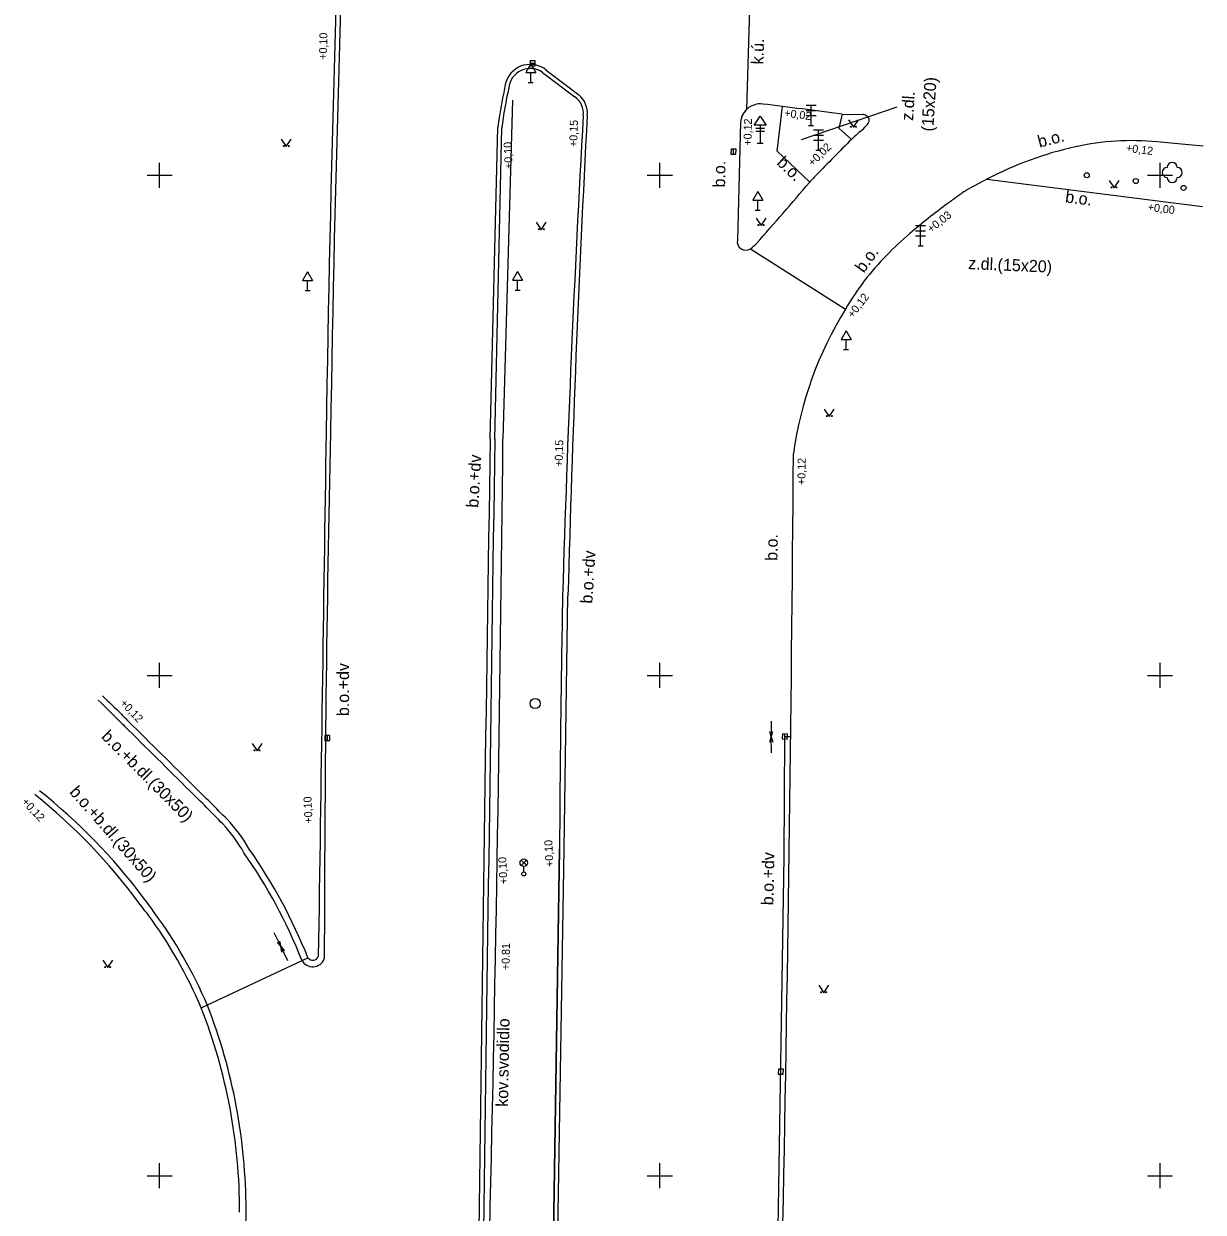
# Model space of a CAD drawing. Extents: x -599151 to -598424, y -1163476 to -1161924.
# Drawn here: x -598681.8 to -598622.8, y -1162451.8 to -1162392.4 of the extents above; entities that cross this region are included whole.
import ezdxf

# ---------------------------------------------------------------- set-up
doc = ezdxf.new("R2010")
doc.units = 0
for name, color, linetype in [('Vrstva 14', 7, 'Continuous'), ('Vrstva 15', 7, 'Continuous'), ('Vrstva 19', 7, 'Continuous'), ('Vrstva 21', 7, 'Continuous'), ('Vrstva 25', 7, 'Continuous'), ('Vrstva 29', 7, 'Continuous'), ('Vrstva 44', 7, 'Continuous'), ('Vrstva 49', 7, 'Continuous'), ('Vrstva 50', 7, 'Continuous'), ('Vrstva 62', 7, 'Continuous'), ('Vrstva 63', 7, 'Continuous'), ('Vrstva 7', 7, 'Continuous')]:
    doc.layers.add(name, color=color, linetype=linetype)

msp = doc.modelspace()

# ---------------------------------------------------------------- linework, layer by layer
at = {"layer": 'Vrstva 14'}
for points in [[(-598640.574, -1162397.224), (-598640.324, -1162397.599), (-598640.074, -1162397.224)], [(-598668.924, -1162398.193), (-598668.674, -1162398.568), (-598668.424, -1162398.193)], [(-598627.548, -1162400.257), (-598627.298, -1162400.632), (-598627.048, -1162400.257)], [(-598656.174, -1162402.347), (-598655.924, -1162402.722), (-598655.674, -1162402.347)], [(-598645.187, -1162402.137), (-598644.937, -1162402.512), (-598644.687, -1162402.137)], [(-598641.784, -1162411.685), (-598641.534, -1162412.06), (-598641.284, -1162411.685)], [(-598670.382, -1162428.398), (-598670.132, -1162428.773), (-598669.882, -1162428.398)], [(-598677.843, -1162439.228), (-598677.593, -1162439.603), (-598677.343, -1162439.228)], [(-598642.059, -1162440.48), (-598641.809, -1162440.855), (-598641.559, -1162440.48)]]:
    msp.add_lwpolyline(points, dxfattribs=at)
for centre, radius in [((-598640.449, -1162397.574), 0.025), ((-598640.199, -1162397.574), 0.025), ((-598668.799, -1162398.543), 0.025), ((-598668.549, -1162398.543), 0.025), ((-598624.39, -1162399.861), 0.00025), ((-598627.423, -1162400.607), 0.025), ((-598627.173, -1162400.607), 0.025), ((-598656.049, -1162402.697), 0.025), ((-598655.799, -1162402.697), 0.025), ((-598645.062, -1162402.487), 0.025), ((-598644.812, -1162402.487), 0.025), ((-598641.659, -1162412.035), 0.025), ((-598641.409, -1162412.035), 0.025), ((-598670.257, -1162428.748), 0.025), ((-598670.007, -1162428.748), 0.025), ((-598677.718, -1162439.578), 0.025), ((-598677.468, -1162439.578), 0.025), ((-598641.934, -1162440.83), 0.025), ((-598641.684, -1162440.83), 0.025)]:
    msp.add_circle(centre, radius, dxfattribs=at)
for centre, start, end in [((-598624.64, -1162399.861), 89.99999, 269.99999), ((-598624.39, -1162399.611), 0, 179.99999), ((-598624.14, -1162399.861), 270, 89.99999), ((-598624.39, -1162400.111), 179.99999, 359.99999)]:
    msp.add_arc(centre, 0.25, start, end, dxfattribs=at)
at = {"layer": 'Vrstva 15'}
for centre, radius in [((-598628.66, -1162400), 0.125), ((-598628.66, -1162400), 0.00025), ((-598626.21, -1162400.29), 0.125), ((-598626.21, -1162400.29), 0.00025), ((-598623.82, -1162400.631), 0.125), ((-598623.82, -1162400.631), 0.00025)]:
    msp.add_circle(centre, radius, dxfattribs=at)
at = {"layer": 'Vrstva 19'}
for p, q in [((-598656.45, -1162394.437), (-598656.7, -1162394.87)), ((-598656.7, -1162394.87), (-598656.2, -1162394.87)), ((-598656.45, -1162394.437), (-598656.2, -1162394.87)), ((-598656.45, -1162395.37), (-598656.45, -1162394.87)), ((-598656.575, -1162395.37), (-598656.325, -1162395.37)), ((-598642.19, -1162396.51), (-598642.69, -1162396.51)), ((-598642.44, -1162397.51), (-598642.44, -1162396.51)), ((-598642.69, -1162396.76), (-598642.19, -1162396.76)), ((-598642.69, -1162397.01), (-598642.19, -1162397.01)), ((-598642.565, -1162397.51), (-598642.315, -1162397.51)), ((-598641.82, -1162397.74), (-598642.32, -1162397.74)), ((-598642.07, -1162398.74), (-598642.07, -1162397.74)), ((-598642.32, -1162397.99), (-598641.82, -1162397.99)), ((-598642.32, -1162398.24), (-598641.82, -1162398.24)), ((-598642.195, -1162398.74), (-598641.945, -1162398.74)), ((-598645.11, -1162400.817), (-598645.36, -1162401.25)), ((-598645.11, -1162400.817), (-598644.86, -1162401.25)), ((-598645.36, -1162401.25), (-598644.86, -1162401.25)), ((-598645.11, -1162401.75), (-598645.11, -1162401.25)), ((-598645.235, -1162401.75), (-598644.985, -1162401.75)), ((-598636.72, -1162402.53), (-598637.22, -1162402.53)), ((-598636.97, -1162403.53), (-598636.97, -1162402.53)), ((-598637.22, -1162402.78), (-598636.72, -1162402.78)), ((-598637.22, -1162403.03), (-598636.72, -1162403.03)), ((-598637.095, -1162403.53), (-598636.845, -1162403.53)), ((-598667.61, -1162404.827), (-598667.86, -1162405.26)), ((-598667.61, -1162404.827), (-598667.36, -1162405.26)), ((-598657.11, -1162404.817), (-598657.36, -1162405.25)), ((-598657.11, -1162404.817), (-598656.86, -1162405.25)), ((-598667.86, -1162405.26), (-598667.36, -1162405.26)), ((-598667.61, -1162405.76), (-598667.61, -1162405.26)), ((-598657.36, -1162405.25), (-598656.86, -1162405.25)), ((-598657.11, -1162405.75), (-598657.11, -1162405.25)), ((-598667.735, -1162405.76), (-598667.485, -1162405.76)), ((-598657.235, -1162405.75), (-598656.985, -1162405.75)), ((-598640.69, -1162407.777), (-598640.94, -1162408.21)), ((-598640.69, -1162407.777), (-598640.44, -1162408.21)), ((-598640.94, -1162408.21), (-598640.44, -1162408.21)), ((-598640.69, -1162408.71), (-598640.69, -1162408.21)), ((-598640.815, -1162408.71), (-598640.565, -1162408.71))]:
    msp.add_line(p, q, dxfattribs=at)
at = {"layer": 'Vrstva 21'}
msp.add_lwpolyline([(-598657.37, -1162396.24), (-598657.84, -1162413.18)], dxfattribs=at)
msp.add_arc((-601785.869, -1162380.888), 3128.195, 358.68275, 359.408531, dxfattribs=at)
at = {"layer": 'Vrstva 25'}
for p, q in [((-598656.475, -1162394.4), (-598656.225, -1162394.4)), ((-598646.325, -1162398.945), (-598646.315, -1162398.695)), ((-598666.62, -1162428.005), (-598666.62, -1162428.255)), ((-598643.755, -1162428.175), (-598643.745, -1162427.925)), ((-598643.955, -1162444.925), (-598643.945, -1162444.675))]:
    msp.add_line(p, q, dxfattribs=at)
for points in [[(-598656.475, -1162394.525), (-598656.225, -1162394.525), (-598656.225, -1162394.275), (-598656.475, -1162394.275)], [(-598646.2, -1162398.95), (-598646.19, -1162398.7), (-598646.44, -1162398.69), (-598646.45, -1162398.94)], [(-598666.745, -1162428.005), (-598666.745, -1162428.255), (-598666.495, -1162428.255), (-598666.495, -1162428.005)], [(-598643.63, -1162428.18), (-598643.62, -1162427.93), (-598643.87, -1162427.92), (-598643.88, -1162428.17)], [(-598643.83, -1162444.93), (-598643.82, -1162444.68), (-598644.07, -1162444.67), (-598644.08, -1162444.92)]]:
    msp.add_lwpolyline(points, close=True, dxfattribs=at)
msp.add_circle((-598656.23, -1162426.4), 0.25, dxfattribs=at)
at = {"layer": 'Vrstva 29'}
for p, q in [((-598656.932, -1162434.489), (-598656.668, -1162434.225)), ((-598656.664, -1162434.488), (-598656.928, -1162434.223)), ((-598656.8, -1162434.82), (-598656.8, -1162434.545))]:
    msp.add_line(p, q, dxfattribs=at)
for centre, radius in [((-598656.8, -1162434.357), 0.188), ((-598656.8, -1162434.92), 0.1)]:
    msp.add_circle(centre, radius, dxfattribs=at)
at = {"layer": 'Vrstva 44'}
for p, q in [((-598645.21, -1162397.641), (-598644.762, -1162397.641)), ((-598645.21, -1162397.791), (-598644.767, -1162397.791)), ((-598644.99, -1162397.491), (-598644.99, -1162398.391)), ((-598645.14, -1162398.391), (-598644.84, -1162398.391))]:
    msp.add_line(p, q, dxfattribs=at)
msp.add_lwpolyline([(-598645.29, -1162397.496), (-598644.99, -1162397.041), (-598644.69, -1162397.496)], close=True, dxfattribs=at)
at = {"layer": 'Vrstva 49'}
for p, q in [((-598642.914, -1162398.215), (-598638.13, -1162396.579)), ((-598644.441, -1162427.278), (-598644.431, -1162428.07)), ((-598644.431, -1162428.07), (-598644.508, -1162427.801)), ((-598644.499, -1162428.339), (-598644.431, -1162428.07)), ((-598644.363, -1162427.799), (-598644.431, -1162428.07)), ((-598644.421, -1162428.861), (-598644.431, -1162428.07)), ((-598644.431, -1162428.07), (-598644.355, -1162428.339)), ((-598669.299, -1162437.844), (-598668.947, -1162438.553)), ((-598669.003, -1162438.28), (-598668.947, -1162438.553)), ((-598668.947, -1162438.553), (-598669.134, -1162438.344)), ((-598668.595, -1162439.262), (-598668.947, -1162438.553)), ((-598668.892, -1162438.826), (-598668.947, -1162438.553)), ((-598668.947, -1162438.553), (-598668.762, -1162438.762))]:
    msp.add_line(p, q, dxfattribs=at)
at = {"layer": 'Vrstva 62'}
for p, q in [((-598675, -1162400.625), (-598675, -1162399.375)), ((-598650, -1162400.625), (-598650, -1162399.375)), ((-598625, -1162400.625), (-598625, -1162399.375)), ((-598675.625, -1162400), (-598674.375, -1162400)), ((-598650.625, -1162400), (-598649.375, -1162400)), ((-598625.625, -1162400), (-598624.375, -1162400)), ((-598675, -1162425.625), (-598675, -1162424.375)), ((-598650, -1162425.625), (-598650, -1162424.375)), ((-598625, -1162425.625), (-598625, -1162424.375)), ((-598675.625, -1162425), (-598674.375, -1162425)), ((-598650.625, -1162425), (-598649.375, -1162425)), ((-598625.625, -1162425), (-598624.375, -1162425)), ((-598675, -1162450.625), (-598675, -1162449.375)), ((-598650, -1162450.625), (-598650, -1162449.375)), ((-598625, -1162450.625), (-598625, -1162449.375)), ((-598675.625, -1162450), (-598674.375, -1162450)), ((-598650.625, -1162450), (-598649.375, -1162450)), ((-598625.625, -1162450), (-598624.375, -1162450))]:
    msp.add_line(p, q, dxfattribs=at)
at = {"layer": 'Vrstva 63'}
for points in [[(-598645.65, -1162396.7), (-598645.48, -1162391.11)], [(-598655.86, -1162394.86), (-598654.25, -1162396.08)], [(-598658.25, -1162413.19), (-598657.9, -1162397.63)], [(-598645.97, -1162397.36), (-598646.12, -1162403.24)], [(-598645.47, -1162403.68), (-598640.72, -1162406.69)], [(-598655.01, -1162433.67), (-598655.31, -1162452.9), (-598655.81, -1162473.2), (-598656.5, -1162493.58), (-598657.72, -1162513.16), (-598659.63, -1162532.7), (-598662.2, -1162552.27)], [(-598672.92, -1162441.61), (-598667.59, -1162439.11)]]:
    msp.add_lwpolyline(points, dxfattribs=at)
for centre, radius, start, end in [((-597162.6, -1162436.919), 1504.272, 177.606603, 179.083942), ((-598656.482, -1162395.733), 1.072, 54.53285, 175.01745), ((-598637.068, -1162400.268), 20.999, 167.26723, 172.78252), ((-598654.809, -1162396.892), 0.986, 353.13017, 55.47893), ((-598644.969, -1162397.438), 1.004, 132.69782, 175.56947), ((-597758.041, -1162447.465), 897.209, 176.776219, 178.310953), ((-598645.704, -1162403.325), 0.425, 168.39038, 303.41966), ((-598624.943, -1162416.45), 18.552, 148.25926, 172.13175), ((-496767.179, -1163943.948), 101911.003, 179.139175, 179.15389444), ((-514506.267, -1163645.477), 84161.005, 179.16104444, 179.18797778), ((-602002.258, -1162387.313), 3359.044, 358.868233, 359.546325), ((-597761.433, -1162437.94), 893.588, 178.91505, 179.726219), ((-598667.346, -1162438.94), 0.297, 214.81939, 338.3445), ((-598699.015, -1162451.797), 28.013, 359.94124, 21.32433)]:
    msp.add_arc(centre, radius, start, end, dxfattribs=at)
at = {"layer": 'Vrstva 7'}
msp.add_line((-598640.91, -1162396.94), (-598639.87, -1162396.96), dxfattribs=at)
for points in [[(-598655.86, -1162394.86), (-598654.25, -1162396.08)], [(-598655.682, -1162394.745), (-598654.051, -1162395.98)], [(-598642.5, -1162400.351), (-598644.13, -1162398.801), (-598643.871, -1162396.564)], [(-598640.887, -1162396.943), (-598641.05, -1162397.641), (-598640.42, -1162398.211)], [(-598658.48, -1162413.17), (-598658.1, -1162397.615)], [(-598658.25, -1162413.19), (-598657.9, -1162397.63)], [(-598645.97, -1162397.36), (-598646.12, -1162403.24)], [(-598622.84, -1162398.551), (-598623.932, -1162398.446), (-598625.15, -1162398.331)], [(-598633.65, -1162400.201), (-598622.87, -1162401.561)], [(-598654.79, -1162433.67), (-598654.592, -1162421.028)], [(-598644.11, -1162453.65), (-598643.78, -1162434.06), (-598643.75, -1162428.05), (-598643.462, -1162428.053)], [(-598655.31, -1162452.9), (-598655.01, -1162433.67)], [(-598655.09, -1162452.9), (-598654.79, -1162433.67)], [(-598668.38, -1162499.186), (-598668.328, -1162498.546), (-598670.963, -1162474.131), (-598670.93, -1162472.7), (-598670.682, -1162451.734)]]:
    msp.add_lwpolyline(points, dxfattribs=at)
for centre, radius, start, end in [((-597162.6, -1162436.919), 1504.272, 177.606603, 179.083958), ((-597164.99, -1162437.641), 1501.675, 177.575294, 179.054467), ((-598656.482, -1162395.733), 1.272, 51.00091, 159.32081), ((-598656.482, -1162395.733), 1.072, 54.53285, 175.01743), ((-598637.068, -1162400.268), 21.199, 166.40116, 172.81107), ((-598637.068, -1162400.268), 20.999, 167.26723, 172.78252), ((-598654.809, -1162396.892), 0.986, 353.13017, 55.47893), ((-598654.809, -1162396.892), 1.186, 353.46923, 50.265), ((-598644.969, -1162397.438), 1.004, 83.73637, 175.56947), ((-598764.385, -1163356.54), 967.511, 82.667844, 82.903631), ((-597758.041, -1162447.465), 897.209, 176.776219, 178.310953), ((-597758.146, -1162444.892), 896.763, 176.940372, 178.475106), ((-598639.921, -1162397.449), 0.491, 59.85861, 84.05077), ((-598639.829, -1162397.291), 0.309, 29.22625, 59.85861), ((-598640.065, -1162397.146), 0.545, 316.51735, 343.85566), ((-598639.738, -1162397.24), 0.204, 343.85566, 29.22625), ((-598635.966, -1162402.682), 6.312, 129.63634, 134.88552), ((-598642.336, -1162394.992), 3.675, 309.63634, 316.51735), ((-598531.061, -1162508.092), 155.027, 134.86349, 135.79255), ((-598626.396, -1162411.414), 13.143, 84.55967, 102.40742), ((-598625.439, -1162415.761), 17.594, 102.40742, 117.81729), ((-598635.773, -1162406.232), 8.945, 135.81458, 139.19006), ((-598599.962, -1162464.049), 72.191, 117.81729, 118.71508), ((-598879.707, -1162197.725), 311.959, 318.75095, 319.49184), ((-598624.666, -1162415.659), 17.96, 124.34877, 125.60453), ((-598633.765, -1162402.345), 1.835, 118.71508, 124.34877), ((-598614.575, -1162429.915), 35.426, 126.42476, 130.33726), ((-598610.614, -1162435.284), 42.098, 125.60453, 126.42476), ((-598645.704, -1162403.325), 0.425, 168.39038, 303.41966), ((-598627.642, -1162414.527), 15.238, 130.33726, 136.3043), ((-598653.428, -1162394.23), 12.354, 310.10147, 312.00816), ((-598629.374, -1162413.245), 13.103, 135.1891, 149.98432), ((-598634.093, -1162408.364), 6.317, 136.3043, 136.43078), ((-598624.943, -1162416.45), 18.552, 148.25926, 172.13175), ((-496767.191, -1163943.946), 101910.991, 179.139175, 179.15389444), ((-597432.426, -1162440.651), 1234.347, 178.709894, 179.931167), ((-587520.198, -1162590.555), 11139.694, 179.0876056, 179.2912), ((-514506.27, -1163645.477), 84161.002, 179.16104167, 179.18797778), ((-602002.258, -1162387.313), 3359.044, 358.868233, 359.546325), ((-597761.433, -1162437.94), 893.588, 178.91505, 179.726219), ((-584130.02, -1147767.941), 20652.145, 225.2162667, 225.2204972), ((-581593.876, -1145212.497), 24252.159, 225.2164028, 225.2195139), ((-595925.38, -1159654.235), 3906.254, 225.219547, 225.2273), ((-595925.544, -1159654.401), 3906.331, 225.222595, 225.2273), ((-589878.568, -1153559.255), 12492.175, 225.2272991, 225.2484611), ((-589878.567, -1153559.254), 12491.867, 225.2272992, 225.2484611), ((-600864.968, -1164641.351), 3113.064, 45.206055, 45.248417), ((-598699.392, -1162453.601), 29.027, 36.42849, 51.29144), ((-598698.895, -1162453.385), 28.839, 36.84915, 51.66677), ((-598771.789, -1162530.723), 140.19, 44.52993, 45.47297), ((-598677.755, -1162437.874), 8.363, 30.10058, 42.90887), ((-598677.307, -1162437.515), 7.472, 29.23259, 43.0904), ((-598692.331, -1162448.955), 26.303, 21.6979, 35.00424), ((-598692.331, -1162448.955), 26.628, 21.6979, 35.00424), ((-598688.12, -1162446.111), 15.523, 35.84903, 38.89011), ((-598689.421, -1162446.539), 17.154, 34.59398, 37.52792), ((-598694.182, -1162450.687), 23.119, 23.11824, 36.42459), ((-598694.059, -1162450.676), 23.333, 23.18372, 36.49006), ((-598667.346, -1162438.94), 0.617, 207.96887, 338.3445), ((-598667.346, -1162438.94), 0.297, 214.81939, 338.3445), ((-598699.015, -1162451.797), 28.013, 359.94124, 21.32433), ((-598698.974, -1162451.757), 28.293, 0.04601, 21.27684)]:
    msp.add_arc(centre, radius, start, end, dxfattribs=at)

# ---------------------------------------------------------------- texts
at = {"layer": 'Vrstva 49'}
for s, height, rotation, p in [('k.ú.', 0.6, 88.25809, (-598644.824, -1162394.468)), ('(15x20)', 0.6, 86.37063, (-598636.337, -1162397.826)), ('z.dl.', 0.6, 86.37063, (-598637.345, -1162397.291)), ('b.o.', 0.6, 14.5846, (-598631.025, -1162398.625)), ('b.o.', 0.6, 316.4411, (-598644.196, -1162399.422)), ('b.o.', 0.6, 89.03493, (-598646.741, -1162400.616)), ('b.o.', 0.6, 352.80958, (-598629.762, -1162401.352)), ('b.o.', 0.6, 54.46012, (-598639.806, -1162404.917)), ('z.dl.(15x20)', 0.59998, 357.48464, (-598634.598, -1162404.689)), ('b.o.+dv', 0.6, 86.60985, (-598659.076, -1162416.628)), ('b.o.', 0.6, 89.03493, (-598644.127, -1162419.275)), ('b.o.+dv', 0.6, 86.60985, (-598653.373, -1162421.422)), ('b.o.+dv', 0.6, 89.95059, (-598665.535, -1162427.032)), ('b.o.+b.dl.(30x50)', 0.6, 314.93049, (-598677.952, -1162428.09)), ('b.o.+b.dl.(30x50)', 0.6, 311.39106, (-598679.541, -1162430.848)), ('b.o.+dv', 0.6, 88.70906, (-598644.328, -1162436.49)), ('kov.svodidlo', 0.59996, 88.96455, (-598657.59, -1162446.557))]:
    msp.add_text(s, height=height, rotation=rotation, dxfattribs=at).set_placement(p)
at = {"layer": 'Vrstva 50'}
for s, rotation, p in [('+0,10', 88.46423, (-598666.648, -1162394.233)), ('+0,02', 352.72622, (-598643.799, -1162397.076)), ('+0,15', 88.26431, (-598654.133, -1162398.594)), ('+0,12', 89.03493, (-598645.418, -1162398.523)), ('+0,10', 92.49334, (-598657.355, -1162399.678)), ('+0,02', 44.73238, (-598642.354, -1162399.582)), ('+0,12', 352.80958, (-598626.718, -1162398.823)), ('+0,00', 352.80958, (-598625.632, -1162401.775)), ('+0,03', 38.34397, (-598636.443, -1162402.899)), ('+0,12', 52.30382, (-598640.348, -1162407.165)), ('+0,15', 88.26431, (-598654.864, -1162414.581)), ('+0,12', 89.03493, (-598642.73, -1162415.483)), ('+0,12', 313.29736, (-598677.008, -1162426.406)), ('+0,10', 92.49334, (-598667.356, -1162432.394)), ('+0,12', 313.29736, (-598681.923, -1162431.345)), ('+0,10', 92.49334, (-598655.32, -1162434.564)), ('+0,10', 92.49334, (-598657.617, -1162435.415)), ('+0.81', 89.14576, (-598657.512, -1162439.73))]:
    msp.add_text(s, height=0.4, rotation=rotation, dxfattribs=at).set_placement(p)

doc.saveas('drawing.dxf')
